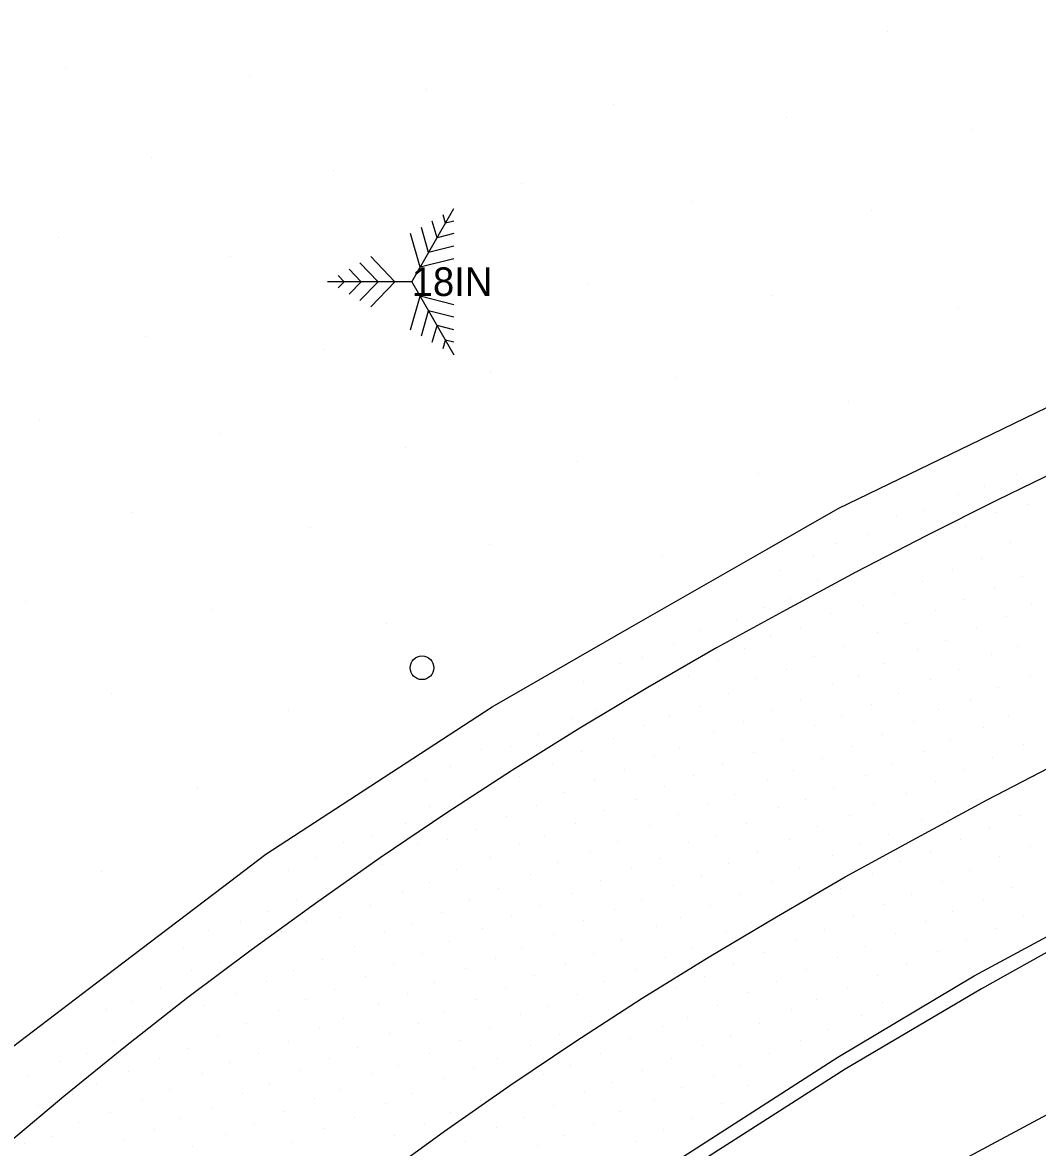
# Model space of a CAD drawing. Extents: x 1732346 to 1733076, y 467730 to 468633.
# Drawn here: x 1732473.7 to 1732537.7, y 467897.3 to 467968.3 of the extents above; entities that cross this region are included whole.
import ezdxf

# ---------------------------------------------------------------- set-up
doc = ezdxf.new("R2010")
doc.units = 0
for name, color, linetype in [('Default', 7, 'Continuous'), ('S_Ground_SpotElevation', 7, 'Continuous'), ('S_Guardrail_Beam', 7, 'Continuous'), ('S_Roadway_Edge_Pavement', 7, 'Continuous'), ('S_Roadway_Painted_Lines', 7, 'Continuous'), ('S_Text', 7, 'Continuous'), ('S_Traffic_Posts', 7, 'Continuous'), ('S_Trees_Bush_Line', 7, 'Continuous'), ('S_Trees_Conifer_Pay', 7, 'Continuous')]:
    doc.layers.add(name, color=color, linetype=linetype)

# ---------------------------------------------------------------- blocks, each defined once
blk = doc.blocks.new('POINT_DISPLAY')
at = {"layer": 'Default'}
blk.add_line((0, 0), (0, 0), dxfattribs=at)

msp = doc.modelspace()

# ---------------------------------------------------------------- linework, layer by layer
at = {"layer": 'S_Guardrail_Beam'}
msp.add_lwpolyline([(1732607.282, 467936.263), (1732588.104, 467930.706), (1732570.186, 467924.34), (1732565.348, 467922.428), (1732556.167, 467918.53), (1732548.929, 467915.173), (1732540.057, 467910.614), (1732534.161, 467907.31), (1732525.552, 467902.255), (1732511.606, 467893.322), (1732506.274, 467889.585), (1732498.266, 467883.63), (1732493.658, 467879.989), (1732485.911, 467873.702), (1732484.627, 467872.615), (1732477.092, 467866.042), (1732475.928, 467864.959), (1732468.681, 467858.101)], dxfattribs=at)
at = {"layer": 'S_Roadway_Edge_Pavement'}
for points in [[(1732470.352, 467901.632), (1732478.314, 467907.682), (1732486.277, 467913.732), (1732488.997, 467915.8), (1732497.374, 467921.261), (1732503.277, 467925.109), (1732511.956, 467930.076), (1732520.635, 467935.044), (1732525.104, 467937.603), (1732534.106, 467941.959), (1732542.485, 467946.013), (1732551.645, 467950.024), (1732556.846, 467952.301), (1732566.195, 467955.849), (1732572.88, 467958.385), (1732582.37, 467961.536), (1732590.954, 467964.387), (1732600.62, 467966.947), (1732605.6, 467968.266)], [(1732468.114, 467858.675), (1732475.358, 467865.577), (1732476.524, 467866.662), (1732484.062, 467873.238), (1732485.365, 467874.342), (1732493.131, 467880.644), (1732497.761, 467884.302), (1732505.819, 467890.235), (1732511.134, 467894.017), (1732525.087, 467903.004), (1732533.681, 467908.129), (1732539.657, 467911.354), (1732548.555, 467915.926), (1732555.817, 467919.295), (1732565.021, 467923.202), (1732569.881, 467925.124), (1732587.847, 467931.506), (1732607.065, 467937.025)]]:
    msp.add_lwpolyline(points, dxfattribs=at)
at = {"layer": 'S_Roadway_Painted_Lines'}
for points in [[(1732539.639, 467940.316), (1732535.134, 467938.142), (1732530.665, 467935.896), (1732526.227, 467933.589), (1732521.822, 467931.221), (1732517.438, 467928.813), (1732513.105, 467926.312), (1732508.81, 467923.748), (1732504.562, 467921.107), (1732500.371, 467918.375), (1732496.226, 467915.575), (1732492.132, 467912.701), (1732488.09, 467909.755), (1732484.081, 467906.763), (1732480.144, 467903.678), (1732476.265, 467900.52), (1732472.434, 467897.304)], [(1732496.26, 467895.403), (1732500.283, 467898.329), (1732504.391, 467901.211), (1732508.556, 467904.003), (1732512.748, 467906.721), (1732516.963, 467909.323), (1732521.218, 467911.86), (1732525.563, 467914.368), (1732530.066, 467916.829), (1732534.519, 467919.233), (1732538.972, 467921.55)]]:
    msp.add_lwpolyline(points, dxfattribs=at)
at = {"layer": 'S_Traffic_Posts'}
msp.add_circle((1732498.858, 467927.566), 0.749, dxfattribs=at)
at = {"layer": 'S_Trees_Bush_Line'}
msp.add_lwpolyline([(1732378.868, 467730.204), (1732418.683, 467785.255), (1732451.458, 467829.569), (1732481.42, 467856.922), (1732516.442, 467887.667), (1732559.006, 467910.479), (1732592.363, 467920.81), (1732609.829, 467928.982), (1732642.363, 467934.2)], dxfattribs=at)
at = {"layer": 'S_Trees_Conifer_Pay'}
for p, q in [((1732498.211, 467951.917), (1732500.874, 467956.528)), ((1732499.806, 467954.681), (1732499.505, 467955.737)), ((1732500.34, 467955.605), (1732500.19, 467956.134)), ((1732500.874, 467955.737), (1732500.34, 467955.605)), ((1732498.743, 467952.84), (1732498.136, 467954.946)), ((1732499.277, 467953.761), (1732498.82, 467955.34)), ((1732500.874, 467954.946), (1732499.806, 467954.681)), ((1732497.145, 467951.917), (1732495.625, 467953.499)), ((1732500.874, 467954.158), (1732499.277, 467953.761)), ((1732496.082, 467951.917), (1732494.941, 467953.102)), ((1732500.874, 467953.364), (1732498.743, 467952.84)), ((1732493.95, 467951.917), (1732493.572, 467952.311)), ((1732495.016, 467951.917), (1732494.256, 467952.705)), ((1732498.211, 467951.917), (1732492.887, 467951.917)), ((1732493.572, 467951.523), (1732493.95, 467951.917)), ((1732494.256, 467951.126), (1732495.016, 467951.917)), ((1732494.941, 467950.729), (1732496.082, 467951.917)), ((1732495.625, 467950.335), (1732497.145, 467951.917)), ((1732498.211, 467951.917), (1732500.874, 467947.306)), ((1732498.136, 467948.888), (1732498.743, 467950.994)), ((1732500.874, 467950.467), (1732498.743, 467950.994)), ((1732498.82, 467948.491), (1732499.277, 467950.071)), ((1732500.874, 467949.676), (1732499.277, 467950.071)), ((1732499.505, 467948.094), (1732499.806, 467949.15)), ((1732500.874, 467948.888), (1732499.806, 467949.15)), ((1732500.19, 467947.7), (1732500.34, 467948.229)), ((1732500.874, 467948.094), (1732500.34, 467948.229))]:
    msp.add_line(p, q, dxfattribs=at)

# ---------------------------------------------------------------- block references
at = {"layer": 'S_Ground_SpotElevation'}
for p in [(1732528.249, 467967.699), (1732476.351, 467965.415), (1732487.989, 467964.834), (1732499.125, 467964.012), (1732510.939, 467963.085), (1732521.846, 467962.282), (1732533.598, 467961.513), (1732481.767, 467959.727), (1732493.301, 467958.949), (1732505.137, 467958.079), (1732515.942, 467956.986), (1732527.226, 467956.379), (1732475.956, 467954.712), (1732486.79, 467953.509), (1732498.26, 467951.785), (1732509.367, 467951.723), (1732520.953, 467951.072), (1732532.686, 467950.305), (1732481.384, 467948.489), (1732492.722, 467947.636), (1732503.207, 467946.237), (1732514.905, 467945.9), (1732525.785, 467944.356), (1732474.719, 467943.223), (1732486.057, 467942.335), (1732497.812, 467941.466), (1732508.686, 467940.592), (1732520.104, 467939.798), (1732536.357, 467939.74), (1732534.368, 467939.009), (1732532.696, 467938.477), (1732537.062, 467937.847), (1732480.616, 467937.327), (1732530.558, 467937.494), (1732535.117, 467937.362), (1732528.784, 467937.12), (1732533.114, 467936.452), (1732491.835, 467936.382), (1732526.979, 467935.965), (1732531.316, 467935.901), (1732503.121, 467935.361), (1732524.989, 467935.395), (1732535.952, 467935.466), (1732514.012, 467934.65), (1732523.528, 467934.58), (1732529.545, 467934.973), (1732534.143, 467934.482), (1732521.456, 467933.706), (1732526.103, 467933.658), (1732527.765, 467934.151), (1732532.337, 467933.786), (1732523.838, 467933.12), (1732530.407, 467933.013), (1732536.71, 467933.342), (1732528.663, 467932.253), (1732534.963, 467932.648), (1732473.814, 467931.718), (1732522.086, 467931.923), (1732526.725, 467931.486), (1732532.999, 467931.87), (1732537.309, 467931.534), (1732485.578, 467931.212), (1732520.484, 467931.372), (1732524.614, 467930.957), (1732531.225, 467931.155), (1732535.747, 467930.825), (1732496.637, 467930.326), (1732518.689, 467930.596), (1732522.718, 467930.131), (1732529.341, 467930.378), (1732533.827, 467930.132), (1732516.433, 467929.946), (1732520.818, 467929.604), (1732527.606, 467929.805), (1732514.695, 467929.077), (1732519.198, 467928.753), (1732525.492, 467928.889), (1732530.147, 467928.686), (1732531.884, 467929.307), (1732536.405, 467928.912), (1732512.759, 467928.196), (1732517.587, 467928.024), (1732523.587, 467928.299), (1732534.789, 467928.372), (1732511.286, 467927.821), (1732521.873, 467927.477), (1732527.972, 467927.864), (1732532.694, 467927.43), (1732509.072, 467926.668), (1732515.695, 467927.066), (1732519.988, 467926.861), (1732524.772, 467926.56), (1732526.377, 467927.027), (1732530.946, 467926.796), (1732537.226, 467927.074), (1732479.266, 467925.962), (1732511.831, 467926.167), (1732513.788, 467926.399), (1732518.221, 467925.926), (1732528.938, 467925.964), (1732535.236, 467926.35), (1732516.339, 467925.149), (1732522.735, 467925.564), (1732527.228, 467925.233), (1732533.452, 467925.568), (1732490.411, 467924.896), (1732509.781, 467924.883), (1732514.472, 467924.504), (1732520.897, 467924.842), (1732525.319, 467924.486), (1732531.431, 467924.912), (1732535.886, 467924.563), (1732508.368, 467924.358), (1732512.874, 467923.937), (1732519.144, 467924.166), (1732523.588, 467923.947), (1732529.871, 467924.151), (1732534.282, 467923.806), (1732506.187, 467923.352), (1732510.959, 467923.084), (1732517.247, 467923.565), (1732521.601, 467923), (1732527.901, 467923.337), (1732532.213, 467923.047), (1732502.637, 467922.406), (1732504.417, 467922.609), (1732508.942, 467922.252), (1732515.089, 467922.559), (1732526.032, 467922.6), (1732530.491, 467922.294), (1732536.815, 467922.746), (1732513.529, 467922.033), (1732519.74, 467922.201), (1732524.152, 467921.847), (1732534.86, 467921.903), (1732500.632, 467921.333), (1732507.093, 467921.464), (1732511.616, 467921.142), (1732517.839, 467921.473), (1732522.299, 467921.082), (1732528.536, 467921.48), (1732533.105, 467921.147), (1732499.07, 467920.454), (1732503.323, 467920.331), (1732505.015, 467920.706), (1732509.742, 467920.452), (1732515.994, 467920.767), (1732520.633, 467920.485), (1732526.85, 467920.795), (1732531.265, 467920.419), (1732537.519, 467920.723), (1732484.691, 467920.025), (1732501.407, 467919.531), (1732507.76, 467919.687), (1732514.15, 467920.053), (1732518.591, 467919.594), (1732524.804, 467919.958), (1732529.438, 467919.651), (1732535.699, 467920.01), (1732499.359, 467918.822), (1732506.065, 467918.893), (1732512.408, 467919.266), (1732516.878, 467918.942), (1732521.328, 467918.727), (1732523.031, 467919.241), (1732527.35, 467918.935), (1732533.913, 467919.278), (1732504.166, 467918.163), (1732510.371, 467918.568), (1732515.061, 467918.319), (1732525.801, 467918.226), (1732530.349, 467918.012), (1732532.038, 467918.515), (1732536.551, 467918.223), (1732497.797, 467917.761), (1732502.323, 467917.364), (1732508.558, 467917.75), (1732513.198, 467917.589), (1732519.324, 467917.761), (1732523.778, 467917.547), (1732534.638, 467917.424), (1732495.758, 467916.989), (1732500.49, 467916.724), (1732506.577, 467916.974), (1732511.163, 467916.612), (1732517.452, 467917.008), (1732522.024, 467916.753), (1732528.278, 467917.075), (1732532.815, 467916.724), (1732493.877, 467916.534), (1732498.556, 467916.459), (1732505.006, 467916.423), (1732509.483, 467915.973), (1732515.641, 467916.545), (1732520.036, 467915.939), (1732526.474, 467916.4), (1732530.958, 467915.955), (1732537.231, 467916.292), (1732492.181, 467915.571), (1732496.393, 467915.167), (1732503.152, 467915.608), (1732507.388, 467915.267), (1732513.823, 467915.513), (1732518.17, 467915.194), (1732524.767, 467915.724), (1732529.027, 467915.34), (1732535.317, 467915.632), (1732478.637, 467914.706), (1732490.436, 467914.787), (1732494.554, 467914.68), (1732501.038, 467914.81), (1732505.686, 467914.522), (1732512.1, 467914.878), (1732516.506, 467914.452), (1732522.652, 467914.883), (1732527.271, 467914.568), (1732533.403, 467914.776), (1732499.342, 467914.003), (1732510.095, 467914.132), (1732514.726, 467913.857), (1732520.9, 467914.064), (1732531.696, 467914.072), (1732492.863, 467913.672), (1732497.61, 467913.48), (1732503.669, 467913.624), (1732508.318, 467913.347), (1732518.901, 467913.288), (1732525.286, 467913.66), (1732529.739, 467913.291), (1732536.114, 467913.693), (1732490.964, 467912.903), (1732495.626, 467912.559), (1732501.88, 467912.872), (1732506.362, 467912.569), (1732511.008, 467912.338), (1732512.718, 467912.961), (1732517.061, 467912.576), (1732523.449, 467912.992), (1732528.009, 467912.645), (1732534.248, 467912.974), (1732489.098, 467912.176), (1732493.68, 467911.83), (1732500.063, 467912.154), (1732504.485, 467911.921), (1732509.07, 467911.599), (1732515.151, 467911.8), (1732521.557, 467912.222), (1732526.088, 467911.857), (1732532.298, 467912.21), (1732536.791, 467911.865), (1732485.359, 467910.961), (1732487.417, 467911.556), (1732491.59, 467911.561), (1732498.188, 467911.397), (1732502.683, 467911.105), (1732513.628, 467911.257), (1732519.659, 467911.488), (1732524.24, 467911.079), (1732530.617, 467911.528), (1732535.046, 467911.115), (1732489.75, 467910.636), (1732496.501, 467910.855), (1732500.6, 467910.305), (1732507.162, 467910.727), (1732511.461, 467910.444), (1732518.07, 467910.87), (1732522.47, 467910.387), (1732528.72, 467910.818), (1732533.186, 467910.422), (1732483.829, 467909.944), (1732487.924, 467909.988), (1732494.572, 467909.965), (1732498.912, 467909.553), (1732505.164, 467909.912), (1732509.669, 467909.546), (1732515.846, 467909.929), (1732520.466, 467909.589), (1732526.854, 467909.973), (1732531.352, 467909.656), (1732486.102, 467908.956), (1732492.591, 467909.189), (1732497.061, 467908.837), (1732503.49, 467909.249), (1732507.924, 467908.86), (1732514.196, 467909.305), (1732518.478, 467908.829), (1732525.043, 467909.28), (1732529.426, 467908.879), (1732484.328, 467908.47), (1732490.722, 467908.49), (1732495.296, 467908.084), (1732501.571, 467908.58), (1732505.963, 467908.181), (1732512.378, 467908.537), (1732516.683, 467908.065), (1732523.092, 467908.506), (1732527.591, 467908.125), (1732482.35, 467907.346), (1732489.073, 467907.772), (1732499.621, 467907.703), (1732504.13, 467907.424), (1732510.396, 467907.756), (1732514.935, 467907.382), (1732521.245, 467907.748), (1732525.688, 467907.39), (1732487.147, 467907.009), (1732493.349, 467907.301), (1732497.93, 467907.003), (1732502.227, 467906.628), (1732508.651, 467906.98), (1732513.139, 467906.63), (1732519.482, 467907.081), (1732523.722, 467906.647), (1732478.953, 467906.039), (1732480.538, 467906.539), (1732485.11, 467906.248), (1732489.826, 467905.97), (1732491.487, 467906.616), (1732496.134, 467906.371), (1732506.765, 467906.209), (1732517.498, 467906.237), (1732522.141, 467905.984), (1732527.893, 467906.424), (1732482.981, 467905.826), (1732493.924, 467905.454), (1732500.308, 467905.839), (1732505.069, 467905.683), (1732509.516, 467905.234), (1732511.148, 467905.829), (1732515.621, 467905.518), (1732526.607, 467905.661), (1732481.239, 467904.946), (1732487.777, 467905.095), (1732492.394, 467904.838), (1732498.626, 467905.137), (1732503.146, 467904.866), (1732514.019, 467904.927), (1732520.167, 467905.128), (1732524.515, 467904.747), (1732479.426, 467903.986), (1732485.944, 467904.333), (1732490.432, 467903.975), (1732496.793, 467904.493), (1732501.295, 467904.075), (1732507.525, 467904.445), (1732512.009, 467904.187), (1732518.34, 467904.397), (1732522.745, 467904.069), (1732477.71, 467903.211), (1732484.098, 467903.579), (1732488.537, 467903.202), (1732494.796, 467903.59), (1732499.319, 467903.228), (1732505.719, 467903.762), (1732510.103, 467903.242), (1732516.573, 467903.751), (1732520.799, 467903.254), (1732475.968, 467902.741), (1732482.288, 467902.949), (1732486.734, 467902.655), (1732492.998, 467902.904), (1732497.359, 467902.476), (1732503.628, 467902.901), (1732508.249, 467902.497), (1732514.572, 467902.893), (1732518.885, 467902.493), (1732474.055, 467901.771), (1732480.363, 467902.081), (1732485.036, 467901.999), (1732491.162, 467902.174), (1732495.672, 467901.948), (1732502.115, 467902.271), (1732506.505, 467901.897), (1732512.784, 467902.178), (1732517.233, 467901.809), (1732478.325, 467901.35), (1732482.949, 467900.983), (1732489.265, 467901.37), (1732493.739, 467900.989), (1732500.293, 467901.641), (1732504.694, 467901.141), (1732510.822, 467901.397), (1732515.254, 467901.061), (1732519.448, 467901.201), (1732476.786, 467900.657), (1732481.199, 467900.274), (1732487.533, 467900.705), (1732492.05, 467900.374), (1732498.274, 467900.718), (1732502.534, 467900.254), (1732509.106, 467900.752), (1732513.518, 467900.332), (1732474.68, 467899.931), (1732479.211, 467899.532), (1732485.553, 467899.856), (1732490.142, 467899.578), (1732496.578, 467900.108), (1732507.124, 467899.97), (1732511.402, 467899.57), (1732517.773, 467900.093), (1732477.192, 467898.885), (1732483.598, 467899.105), (1732488.285, 467898.839), (1732494.589, 467899.17), (1732499.02, 467898.838), (1732500.676, 467899.522), (1732505.291, 467899.194), (1732515.913, 467899.163), (1732482.009, 467898.448), (1732486.49, 467898.125), (1732492.634, 467898.523), (1732503.568, 467898.589), (1732509.67, 467898.784), (1732514.082, 467898.461), (1732473.782, 467897.537), (1732475.461, 467897.989), (1732480.066, 467897.714), (1732490.714, 467897.63), (1732497.115, 467898.044), (1732501.6, 467897.704), (1732506.114, 467897.447), (1732507.869, 467898.039), (1732512.296, 467897.667), (1732484.364, 467897.381)]:
    msp.add_blockref('POINT_DISPLAY', p, dxfattribs=at)

# ---------------------------------------------------------------- texts
at = {"layer": 'S_Text'}
msp.add_text('18IN', height=1.8, dxfattribs=at).set_placement((1732498.211, 467951.017))

doc.saveas('drawing.dxf')
